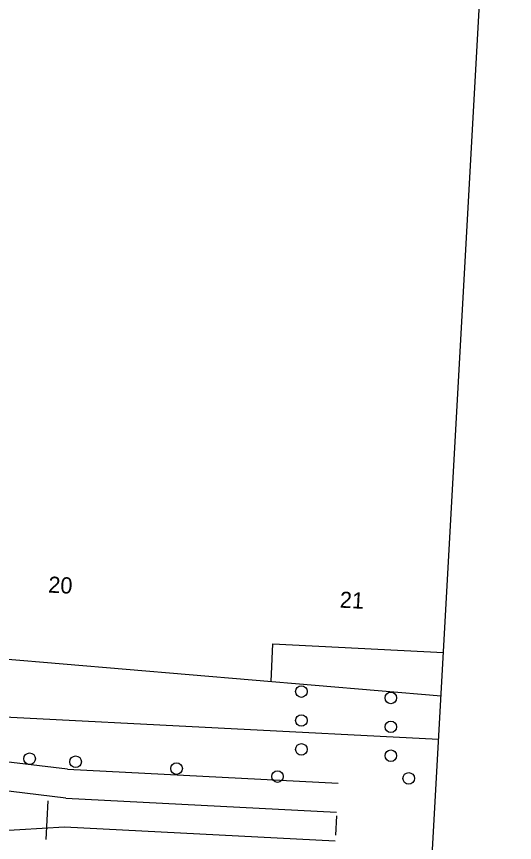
# Model space of a CAD drawing. Extents: x 0 to 1361828, y 0 to 1470398.
# Drawn here: x 681268.7 to 681440.9, y 735115.8 to 735401.5 of the extents above; entities that cross this region are included whole.
import ezdxf

# ---------------------------------------------------------------- set-up
doc = ezdxf.new("R2010")
doc.units = 0
for name, color, linetype in [('$', 7, 'Continuous'), ('border All Plan 20-40_Border 1 - Level 1', 7, 'Continuous'), ('MOT Stage 1', 7, 'Continuous'), ('MOT Stage 1 Lanes', 7, 'Continuous'), ('R_Horz Alg Station', 7, 'Continuous'), ('RW-EX', 7, 'Continuous'), ('RW-PR', 7, 'Continuous')]:
    doc.layers.add(name, color=color, linetype=linetype)

# ---------------------------------------------------------------- blocks, each defined once
blk = doc.blocks.new('BAREL_1508')
at = {"layer": 'MOT Stage 1'}
blk.add_circle((0, 0.01), 2.88, dxfattribs=at)
blk = doc.blocks.new('BAREL_1509')
at = {"layer": 'MOT Stage 1'}
blk.add_circle((0, 0.01), 2.88, dxfattribs=at)
blk = doc.blocks.new('BAREL_1510')
at = {"layer": 'MOT Stage 1'}
blk.add_circle((0, 0.01), 2.88, dxfattribs=at)
blk = doc.blocks.new('BAREL_1511')
at = {"layer": 'MOT Stage 1'}
blk.add_circle((0, 0.01), 2.88, dxfattribs=at)
blk = doc.blocks.new('BAREL_1512')
at = {"layer": 'MOT Stage 1'}
blk.add_circle((0, 0.01), 2.88, dxfattribs=at)
blk = doc.blocks.new('BAREL_1513')
at = {"layer": 'MOT Stage 1'}
blk.add_circle((0, 0.01), 2.88, dxfattribs=at)
blk = doc.blocks.new('BAREL_1529')
at = {"layer": 'MOT Stage 1'}
blk.add_circle((0, 0.01), 2.88, dxfattribs=at)
blk = doc.blocks.new('BAREL_1530')
at = {"layer": 'MOT Stage 1'}
blk.add_circle((0, 0.01), 2.88, dxfattribs=at)
blk = doc.blocks.new('BAREL_1531')
at = {"layer": 'MOT Stage 1'}
blk.add_circle((0, 0.01), 2.88, dxfattribs=at)
blk = doc.blocks.new('BAREL_1538')
at = {"layer": 'MOT Stage 1'}
blk.add_circle((0, 0.01), 2.88, dxfattribs=at)
blk = doc.blocks.new('BAREL_1595')
at = {"layer": 'MOT Stage 1'}
blk.add_circle((0, 0.01), 2.88, dxfattribs=at)

msp = doc.modelspace()

# ---------------------------------------------------------------- linework, layer by layer
at = {"layer": 'border All Plan 20-40_Border 1 - Level 1'}
msp.add_line((681384.1, 734599.57), (681440.93, 735625.3), dxfattribs=at)
at = {"layer": 'MOT Stage 1 Lanes'}
for p, q in [((681286.32, 735141.17), (681230.33, 735147.83)), ((681286.32, 735141.17), (681379.94, 735136.33)), ((681285.8, 735131.19), (681229.82, 735137.84)), ((681285.8, 735131.19), (681379.43, 735126.35)), ((681228.79, 735117.87), (681285.29, 735121.2)), ((681285.29, 735121.2), (681378.91, 735116.36))]:
    msp.add_line(p, q, dxfattribs=at)
at = {"layer": 'R_Horz Alg Station'}
for points in [[(681279.49, 735130.18), (681278.8, 735116.86)], [(681379.36, 735125.02), (681379.02, 735118.36)]]:
    msp.add_lwpolyline(points, dxfattribs=at)
at = {"layer": 'RW-EX'}
msp.add_line((681045.84, 735170.62), (681414.69, 735151.56), dxfattribs=at)
at = {"layer": 'RW-PR'}
for p, q in [((681356.73, 735171.54), (681357.4, 735184.56)), ((681357.4, 735184.56), (681416.35, 735181.51))]:
    msp.add_line(p, q, dxfattribs=at)
msp.add_lwpolyline([(681173.16, 735184.07), (681262.96, 735179.43), (681415.52, 735166.6)], dxfattribs=at)

# ---------------------------------------------------------------- block references
at = {"layer": 'MOT Stage 1', "xscale": 0.6945420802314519, "yscale": 0.6945420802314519, "rotation": 87.04179557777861}
for name, p in [('BAREL_1508', (681367.24, 735168.03)), ('BAREL_1509', (681398.18, 735165.83)), ('BAREL_1510', (681367.24, 735158.03)), ('BAREL_1512', (681398.18, 735155.83)), ('BAREL_1511', (681367.24, 735148.03)), ('BAREL_1513', (681398.18, 735145.83)), ('BAREL_1538', (681273.25, 735144.79)), ('BAREL_1529', (681289.15, 735143.75)), ('BAREL_1530', (681324.07, 735141.39)), ('BAREL_1531', (681358.97, 735138.63)), ('BAREL_1595', (681404.37, 735137.99))]:
    msp.add_blockref(name, p, dxfattribs=at)

# ---------------------------------------------------------------- texts
at = {"layer": '$'}
for s, p in [('20', (681279.59, 735202.27)), ('21', (681380.41, 735197.06))]:
    msp.add_text(s, height=5.6, rotation=357.0415, dxfattribs=at).set_placement(p)

doc.saveas('drawing.dxf')
